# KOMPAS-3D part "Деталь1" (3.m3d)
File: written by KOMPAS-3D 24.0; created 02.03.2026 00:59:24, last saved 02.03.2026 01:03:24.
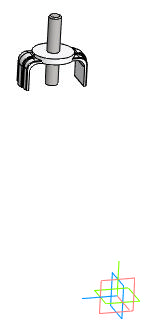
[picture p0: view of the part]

Document properties: Автор: R2D2; Полное имя файла: E:\Работа\Зайцев\GVWR3131M-2W-F-S Задвижка клиновая с выдвижным штоком DN.ru Ду50-200 Ру63\DN100\исходные материалы\3.m3d

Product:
- Body: Твердое тело1  | qty 1
    Масса: 0.571095
- Part/product: Деталь1
    Масса: 0.571095
    additional columns: Типовые

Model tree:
1. Твердое тело1  (labels: Твердое тело1)
2. Эскиз:1
3. Элемент выдавливания:1
     Расстояние 1 = 500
